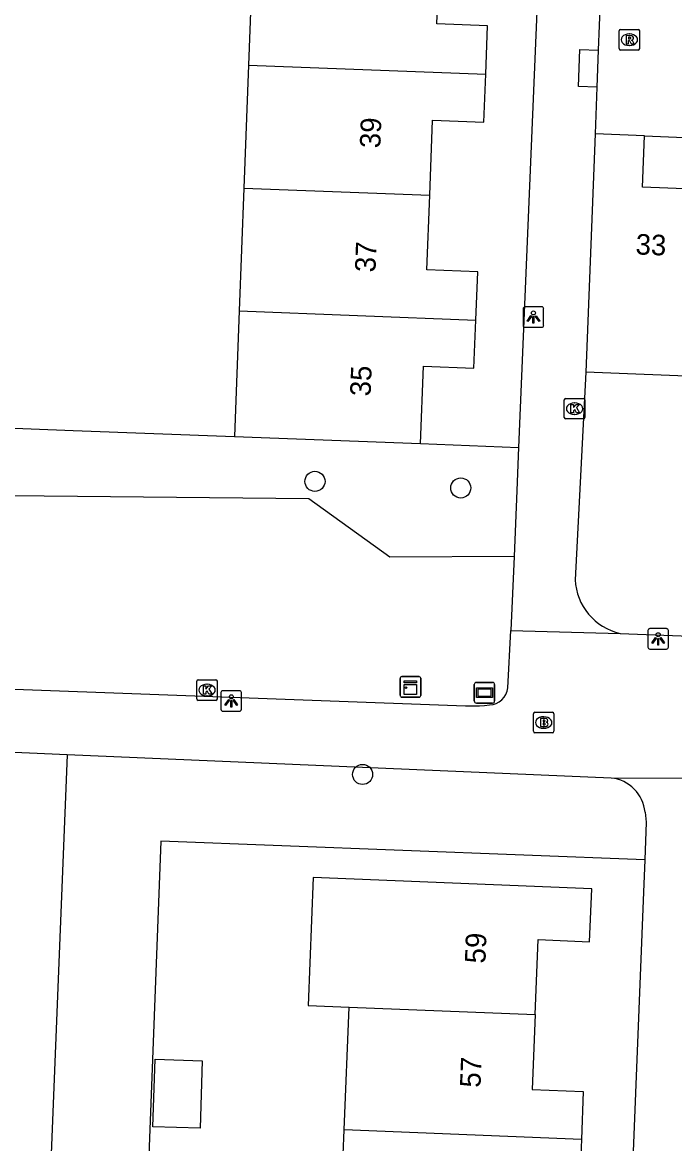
# Model space of a CAD drawing. Extents: x 160787 to 161428, y 386828 to 387483.
# Drawn here: x 161141.1 to 161172.8, y 387264.6 to 387319.2 of the extents above; entities that cross this region are included whole.
import ezdxf

# ---------------------------------------------------------------- set-up
doc = ezdxf.new("R2010")
doc.units = 0
for name, color, linetype in [('IMGEO_Boom', 7, 'Continuous'), ('IMGEO_Brandkraan', 7, 'Continuous'), ('IMGEO_Groenvoorziening', 7, 'Continuous'), ('IMGEO_Kast', 7, 'Continuous'), ('IMGEO_Kolk', 7, 'Continuous'), ('IMGEO_Lichtpunt', 7, 'Continuous'), ('IMGEO_Pand', 7, 'Continuous'), ('IMGEO_Pand_nummerreeks', 7, 'Continuous'), ('IMGEO_Rijbaan_lokaal_open', 7, 'Continuous'), ('IMGEO_Rioolput', 7, 'Continuous'), ('IMGEO_Straatnaambord', 7, 'Continuous'), ('IMGEO_Voetpad_open', 7, 'Continuous')]:
    doc.layers.add(name, color=color, linetype=linetype)

msp = doc.modelspace()

# ---------------------------------------------------------------- linework, layer by layer
at = {"layer": 'IMGEO_Boom'}
for centre in [(161155.308, 387296.861), (161162.4, 387296.541), (161157.626, 387282.603)]:
    msp.add_circle(centre, 0.489, dxfattribs=at)
at = {"layer": 'IMGEO_Brandkraan'}
for p, q in [((161165.935, 387284.701), (161165.935, 387285.553)), ((161166.01, 387285.627), (161166.862, 387285.627)), ((161166.423, 387285.407), (161166.448, 387285.407)), ((161166.936, 387285.553), (161166.936, 387284.701)), ((161166.862, 387284.627), (161166.01, 387284.627)), ((161166.446, 387284.847), (161166.421, 387284.847))]:
    msp.add_line(p, q, dxfattribs=at)
for points in [[(161165.935, 387284.701), (161165.935, 387285.553)], [(161166.01, 387285.627), (161166.862, 387285.627)], [(161166.936, 387285.553), (161166.936, 387284.701)], [(161166.283, 387285.327), (161166.283, 387284.927), (161166.496, 387284.927)], [(161166.514, 387285.327), (161166.283, 387285.327)], [(161166.462, 387285.246), (161166.408, 387285.246), (161166.408, 387285.17)], [(161166.408, 387285.17), (161166.461, 387285.17)], [(161166.47, 387285.094), (161166.408, 387285.094), (161166.408, 387285.013)], [(161166.408, 387285.013), (161166.47, 387285.013)], [(161166.862, 387284.627), (161166.01, 387284.627)]]:
    msp.add_lwpolyline(points, dxfattribs=at)
for centre, radius, start, end in [((161166.012, 387285.551), 0.0765, 91.552, 178.448), ((161166.012, 387285.551), 0.0765, 91.552, 178.448), ((161166.86, 387285.551), 0.0765, 1.552, 88.448), ((161166.86, 387285.551), 0.0765, 1.552, 88.448), ((161166.463, 387285.208), 0.0379, 267.8285, 90.9355), ((161166.471, 387285.053), 0.0404, 269.8759, 90.5077), ((161166.502, 387285.178), 0.251, 268.6676, 293.5347), ((161166.518, 387285.182), 0.145, 59.4692, 91.5367), ((161166.543, 387285.229), 0.0922, 285.5137, 58.1501), ((161166.548, 387285.037), 0.105, 301.3115, 78.989), ((161166.012, 387284.703), 0.0765, 181.552, 268.448), ((161166.012, 387284.703), 0.0765, 181.552, 268.448), ((161166.86, 387284.703), 0.0765, 271.552, 358.448), ((161166.86, 387284.703), 0.0765, 271.552, 358.448)]:
    msp.add_arc(centre, radius, start, end, dxfattribs=at)
for centre, major_axis, ratio, start_param, end_param in [((161166.422, 387285.127), (-0.387, 0.002), 0.722429, 4.712389, 7.853982), ((161166.447, 387285.127), (-0.39, 0.002), 0.717154, 1.570796, 4.712389)]:
    msp.add_ellipse(centre, major_axis=major_axis, ratio=ratio, start_param=start_param, end_param=end_param, dxfattribs=at)
at = {"layer": 'IMGEO_Groenvoorziening'}
for points in [[(161139.046, 387299.512), (161143.553, 387299.341), (161151.391, 387299.041)], [(161160.443, 387298.696), (161165.215, 387298.514)], [(161164.993, 387293.208), (161158.958, 387293.171), (161155.006, 387296.014), (161138.908, 387296.177)], [(161143.258, 387283.56), (161141.91, 387250), (161139.825, 387198.117), (161139.779, 387196.96), (161145.215, 387196.742), (161162.77, 387196.036), (161162.811, 387197.084)], [(161171.353, 387278.449), (161147.813, 387279.35), (161146.59, 387247.494), (161144.751, 387247.564), (161143.809, 387246.052), (161142.905, 387223.679), (161145.53, 387223.573), (161145.284, 387217.483), (161143.51, 387217.555), (161143.326, 387213), (161145.236, 387212.923), (161144.626, 387197.819), (161152.342, 387197.507), (161162.811, 387197.084)]]:
    msp.add_lwpolyline(points, dxfattribs=at)
at = {"layer": 'IMGEO_Kast'}
for p, q in [((161159.454, 387286.435), (161159.454, 387287.276)), ((161159.454, 387287.276), (161159.454, 387286.435)), ((161159.529, 387287.36), (161160.37, 387287.36)), ((161160.37, 387287.36), (161159.529, 387287.36)), ((161160.454, 387287.285), (161160.454, 387286.444)), ((161160.454, 387286.444), (161160.454, 387287.285)), ((161160.379, 387286.36), (161159.538, 387286.36)), ((161159.538, 387286.36), (161160.379, 387286.36))]:
    msp.add_line(p, q, dxfattribs=at)
for points in [[(161159.649, 387287.15), (161160.249, 387287.15), (161160.249, 387287.065), (161159.649, 387287.065), (161159.649, 387287.15)], [(161159.649, 387286.975), (161160.249, 387286.975), (161160.249, 387286.486), (161159.649, 387286.486), (161159.649, 387286.975)]]:
    msp.add_lwpolyline(points, dxfattribs=at)
msp.add_circle((161159.733, 387286.824), 0.0377, dxfattribs=at)
for centre, start, end in [((161159.532, 387287.282), 92.4484, 184.2845), ((161159.532, 387287.282), 92.4484, 184.2845), ((161160.376, 387287.282), 2.4484, 94.2845), ((161160.376, 387287.282), 2.4484, 94.2845), ((161159.532, 387286.438), 182.4484, 274.2845), ((161159.532, 387286.438), 182.4484, 274.2845), ((161160.376, 387286.438), 272.4484, 4.2845), ((161160.376, 387286.438), 272.4484, 4.2845)]:
    msp.add_arc(centre, 0.0779, start, end, dxfattribs=at)
at = {"layer": 'IMGEO_Kolk'}
for p, q in [((161167.439, 387299.973), (161167.439, 387300.825)), ((161167.514, 387300.899), (161168.366, 387300.899)), ((161168.44, 387300.825), (161168.44, 387299.973)), ((161167.927, 387300.679), (161167.952, 387300.679)), ((161168.366, 387299.899), (161167.514, 387299.899)), ((161167.95, 387300.119), (161167.925, 387300.119)), ((161149.558, 387286.281), (161149.558, 387287.133)), ((161149.633, 387287.207), (161150.485, 387287.207)), ((161150.559, 387287.133), (161150.559, 387286.281)), ((161150.046, 387286.987), (161150.071, 387286.987)), ((161150.485, 387286.207), (161149.633, 387286.207)), ((161150.069, 387286.427), (161150.044, 387286.427))]:
    msp.add_line(p, q, dxfattribs=at)
for points in [[(161167.439, 387299.973), (161167.439, 387300.825)], [(161167.514, 387300.899), (161168.366, 387300.899)], [(161168.44, 387300.825), (161168.44, 387299.973)], [(161167.76, 387300.599), (161167.883, 387300.599), (161167.883, 387300.448), (161168.013, 387300.599), (161168.177, 387300.599), (161168.031, 387300.448), (161168.184, 387300.199), (161168.032, 387300.199), (161167.947, 387300.363), (161167.883, 387300.296), (161167.883, 387300.199), (161167.76, 387300.199), (161167.76, 387300.599)], [(161168.366, 387299.899), (161167.514, 387299.899)], [(161149.558, 387286.281), (161149.558, 387287.133)], [(161149.633, 387287.207), (161150.485, 387287.207)], [(161150.559, 387287.133), (161150.559, 387286.281)], [(161149.879, 387286.907), (161150.002, 387286.907), (161150.002, 387286.756), (161150.132, 387286.907), (161150.296, 387286.907), (161150.15, 387286.756), (161150.303, 387286.507), (161150.151, 387286.507), (161150.066, 387286.671), (161150.002, 387286.604), (161150.002, 387286.507), (161149.879, 387286.507), (161149.879, 387286.907)], [(161150.485, 387286.207), (161149.633, 387286.207)]]:
    msp.add_lwpolyline(points, dxfattribs=at)
for centre, start, end in [((161167.516, 387300.823), 91.552, 178.448), ((161167.516, 387300.823), 91.552, 178.448), ((161168.364, 387300.823), 1.552, 88.448), ((161168.364, 387300.823), 1.552, 88.448), ((161167.516, 387299.975), 181.552, 268.448), ((161167.516, 387299.975), 181.552, 268.448), ((161168.364, 387299.975), 271.552, 358.448), ((161168.364, 387299.975), 271.552, 358.448), ((161149.635, 387287.131), 91.552, 178.448), ((161149.635, 387287.131), 91.552, 178.448), ((161150.483, 387287.131), 1.552, 88.448), ((161150.483, 387287.131), 1.552, 88.448), ((161149.635, 387286.283), 181.552, 268.448), ((161149.635, 387286.283), 181.552, 268.448), ((161150.483, 387286.283), 271.552, 358.448), ((161150.483, 387286.283), 271.552, 358.448)]:
    msp.add_arc(centre, 0.0765, start, end, dxfattribs=at)
for centre, major_axis, ratio, start_param, end_param in [((161167.926, 387300.399), (-0.387, 0.002), 0.722429, 4.712389, 7.853982), ((161167.951, 387300.399), (-0.39, 0.002), 0.717154, 1.570796, 4.712389), ((161150.045, 387286.707), (-0.387, 0.002), 0.722429, 4.712389, 7.853982), ((161150.07, 387286.707), (-0.39, 0.002), 0.717154, 1.570796, 4.712389)]:
    msp.add_ellipse(centre, major_axis=major_axis, ratio=ratio, start_param=start_param, end_param=end_param, dxfattribs=at)
at = {"layer": 'IMGEO_Lichtpunt'}
for p, q in [((161165.438, 387305.26), (161165.438, 387304.453)), ((161165.438, 387305.26), (161165.438, 387304.453)), ((161166.34, 387305.355), (161165.532, 387305.355)), ((161166.34, 387305.355), (161165.532, 387305.355)), ((161166.434, 387304.453), (161166.434, 387305.26)), ((161166.434, 387304.453), (161166.434, 387305.26)), ((161165.532, 387304.359), (161166.34, 387304.359)), ((161165.532, 387304.359), (161166.34, 387304.359)), ((161171.504, 387289.6), (161171.504, 387288.793)), ((161171.504, 387289.6), (161171.504, 387288.793)), ((161172.406, 387289.695), (161171.598, 387289.695)), ((161172.406, 387289.695), (161171.598, 387289.695)), ((161172.5, 387288.793), (161172.5, 387289.6)), ((161172.5, 387288.793), (161172.5, 387289.6)), ((161171.598, 387288.699), (161172.406, 387288.699)), ((161171.598, 387288.699), (161172.406, 387288.699)), ((161150.737, 387286.581), (161150.737, 387285.774)), ((161150.737, 387286.581), (161150.737, 387285.774)), ((161151.639, 387286.676), (161150.831, 387286.676)), ((161151.639, 387286.676), (161150.831, 387286.676)), ((161151.733, 387285.774), (161151.733, 387286.581)), ((161151.733, 387285.774), (161151.733, 387286.581)), ((161150.831, 387285.68), (161151.639, 387285.68)), ((161150.831, 387285.68), (161151.639, 387285.68))]:
    msp.add_line(p, q, dxfattribs=at)
for points in [[(161165.812, 387304.924), (161165.851, 387304.896), (161165.663, 387304.634), (161165.625, 387304.661), (161165.812, 387304.924)], [(161165.914, 387304.876), (161165.961, 387304.876), (161165.961, 387304.554), (161165.914, 387304.554), (161165.914, 387304.876)], [(161166.024, 387304.896), (161166.062, 387304.923), (161166.249, 387304.661), (161166.21, 387304.633), (161166.024, 387304.896)], [(161171.878, 387289.264), (161171.917, 387289.236), (161171.729, 387288.974), (161171.691, 387289.001), (161171.878, 387289.264)], [(161172.09, 387289.236), (161172.128, 387289.263), (161172.315, 387289.001), (161172.276, 387288.973), (161172.09, 387289.236)], [(161171.98, 387289.216), (161172.027, 387289.216), (161172.027, 387288.894), (161171.98, 387288.894), (161171.98, 387289.216)], [(161151.111, 387286.245), (161151.15, 387286.217), (161150.962, 387285.955), (161150.924, 387285.982), (161151.111, 387286.245)], [(161151.213, 387286.197), (161151.26, 387286.197), (161151.26, 387285.875), (161151.213, 387285.875), (161151.213, 387286.197)], [(161151.323, 387286.217), (161151.361, 387286.244), (161151.548, 387285.982), (161151.509, 387285.954), (161151.323, 387286.217)]]:
    msp.add_lwpolyline(points, dxfattribs=at)
for centre in [(161165.937, 387305.058), (161172.003, 387289.398), (161151.236, 387286.379)]:
    msp.add_circle(centre, 0.0994, dxfattribs=at)
for centre, start, end in [((161165.532, 387305.26), 90, 180), ((161165.532, 387305.26), 90, 180), ((161166.34, 387305.26), 0, 90), ((161166.34, 387305.26), 0, 90), ((161165.532, 387304.453), 180, 270), ((161165.532, 387304.453), 180, 270), ((161166.34, 387304.453), 270, 0), ((161166.34, 387304.453), 270, 360), ((161171.598, 387289.6), 90, 180), ((161171.598, 387289.6), 90, 180), ((161172.406, 387289.6), 0, 90), ((161172.406, 387289.6), 0, 90), ((161171.598, 387288.793), 180, 270), ((161171.598, 387288.793), 180, 270), ((161172.406, 387288.793), 270, 0), ((161172.406, 387288.793), 270, 360), ((161150.831, 387286.581), 90, 180), ((161150.831, 387286.581), 90, 180), ((161151.639, 387286.581), 0, 90), ((161151.639, 387286.581), 0, 90), ((161150.831, 387285.774), 180, 270), ((161150.831, 387285.774), 180, 270), ((161151.639, 387285.774), 270, 0), ((161151.639, 387285.774), 270, 360)]:
    msp.add_arc(centre, 0.0946, start, end, dxfattribs=at)
at = {"layer": 'IMGEO_Pand'}
for points in [[(161152.31, 387323.131), (161152.081, 387317.118)], [(161163.618, 387316.678), (161163.708, 387319.022), (161161.238, 387319.116), (161161.378, 387322.785)], [(161152.081, 387317.118), (161151.852, 387311.135)], [(161152.081, 387317.118), (161163.618, 387316.678)], [(161160.89, 387310.79), (161161.029, 387314.43), (161163.529, 387314.335), (161163.618, 387316.678)], [(161168.933, 387313.767), (161168.48, 387302.177)], [(161171.343, 387313.673), (161168.933, 387313.767)], [(161174.935, 387311.032), (161171.246, 387311.176), (161171.343, 387313.673)], [(161151.852, 387311.135), (161151.624, 387305.151)], [(161151.852, 387311.135), (161160.89, 387310.79)], [(161163.135, 387304.712), (161163.224, 387307.055), (161160.751, 387307.149), (161160.89, 387310.79)], [(161151.624, 387305.151), (161151.391, 387299.041)], [(161151.624, 387305.151), (161163.135, 387304.712)], [(161160.443, 387298.696), (161160.586, 387302.463), (161163.045, 387302.369), (161163.135, 387304.712)], [(161174.579, 387301.938), (161168.48, 387302.177)], [(161151.391, 387299.041), (161160.443, 387298.696)], [(161166.02, 387270.922), (161166.166, 387274.565), (161168.668, 387274.465), (161168.771, 387277.039), (161157.214, 387277.502), (161155.223, 387277.582), (161154.974, 387271.365), (161156.965, 387271.285)], [(161156.726, 387265.307), (161156.965, 387271.285)], [(161156.965, 387271.285), (161166.02, 387270.922)], [(161166.02, 387270.922), (161165.874, 387267.279), (161168.363, 387267.179), (161168.27, 387264.845)], [(161147.429, 387265.462), (161147.528, 387268.745), (161149.818, 387268.675), (161149.719, 387265.392), (161147.429, 387265.462)], [(161156.486, 387259.313), (161156.726, 387265.307)], [(161168.27, 387264.845), (161156.726, 387265.307)], [(161168.27, 387264.845), (161168.177, 387262.51), (161165.644, 387262.611), (161165.498, 387258.952)]]:
    msp.add_lwpolyline(points, dxfattribs=at)
at = {"layer": 'IMGEO_Rijbaan_lokaal_open'}
for points in [[(161169.235, 387321.452), (161169.093, 387317.844)], [(161169.093, 387317.844), (161169.022, 387316.036)], [(161169.022, 387316.036), (161168.933, 387313.767)], [(161171.343, 387313.673), (161178.722, 387313.364)]]:
    msp.add_lwpolyline(points, dxfattribs=at)
at = {"layer": 'IMGEO_Rioolput'}
for p, q in [((161170.103, 387317.923), (161170.103, 387318.775)), ((161170.178, 387318.849), (161171.03, 387318.849)), ((161171.104, 387318.775), (161171.104, 387317.923)), ((161170.591, 387318.629), (161170.616, 387318.629)), ((161171.03, 387317.849), (161170.178, 387317.849)), ((161170.614, 387318.069), (161170.589, 387318.069))]:
    msp.add_line(p, q, dxfattribs=at)
for points in [[(161170.103, 387317.923), (161170.103, 387318.775)], [(161170.178, 387318.849), (161171.03, 387318.849)], [(161171.104, 387318.775), (161171.104, 387317.923)], [(161170.692, 387318.547), (161170.44, 387318.549), (161170.44, 387318.149)], [(161170.44, 387318.149), (161170.564, 387318.149), (161170.564, 387318.311), (161170.575, 387318.311)], [(161170.618, 387318.468), (161170.564, 387318.468), (161170.564, 387318.387)], [(161170.564, 387318.387), (161170.616, 387318.387)], [(161170.622, 387318.282), (161170.693, 387318.149), (161170.833, 387318.149), (161170.768, 387318.275)], [(161171.03, 387317.849), (161170.178, 387317.849)]]:
    msp.add_lwpolyline(points, dxfattribs=at)
for centre, radius, start, end in [((161170.18, 387318.773), 0.0765, 91.552, 178.448), ((161170.18, 387318.773), 0.0765, 91.552, 178.448), ((161171.028, 387318.773), 0.0765, 1.552, 88.448), ((161171.028, 387318.773), 0.0765, 1.552, 88.448), ((161170.574, 387318.258), 0.0533, 26.0293, 88.6989), ((161170.6, 387318.576), 0.19, 274.7715, 282.9687), ((161170.624, 387318.372), 0.0964, 77.0061, 93.1865), ((161170.638, 387318.429), 0.0378, 276.6634, 79.6772), ((161170.691, 387318.437), 0.109, 350.3612, 89.416), ((161170.689, 387318.437), 0.112, 277.5842, 350.9817), ((161170.673, 387318.222), 0.108, 29.5134, 73.7905), ((161170.18, 387317.925), 0.0765, 181.552, 268.448), ((161170.18, 387317.925), 0.0765, 181.552, 268.448), ((161171.028, 387317.925), 0.0765, 271.552, 358.448), ((161171.028, 387317.925), 0.0765, 271.552, 358.448)]:
    msp.add_arc(centre, radius, start, end, dxfattribs=at)
for centre, major_axis, ratio, start_param, end_param in [((161170.59, 387318.349), (-0.387, 0.002), 0.722429, 4.712389, 7.853982), ((161170.615, 387318.349), (-0.39, 0.002), 0.717154, 1.570796, 4.712389)]:
    msp.add_ellipse(centre, major_axis=major_axis, ratio=ratio, start_param=start_param, end_param=end_param, dxfattribs=at)
at = {"layer": 'IMGEO_Straatnaambord'}
for p, q in [((161163.159, 387287.076), (161163.949, 387287.076)), ((161163.949, 387287.076), (161163.159, 387287.076)), ((161163.059, 387286.176), (161163.059, 387286.976)), ((161163.059, 387286.976), (161163.059, 387286.176)), ((161164.049, 387286.976), (161164.049, 387286.176)), ((161164.049, 387286.176), (161164.049, 387286.976)), ((161163.949, 387286.076), (161163.159, 387286.076)), ((161163.159, 387286.076), (161163.949, 387286.076))]:
    msp.add_line(p, q, dxfattribs=at)
for points in [[(161163.16, 387286.808), (161163.948, 387286.808), (161163.948, 387286.344), (161163.16, 387286.344), (161163.16, 387286.808)], [(161163.225, 387286.743), (161163.225, 387286.409), (161163.883, 387286.409), (161163.883, 387286.743), (161163.225, 387286.743)]]:
    msp.add_lwpolyline(points, dxfattribs=at)
for centre, start, end in [((161163.159, 387286.976), 90, 180), ((161163.159, 387286.976), 90, 180), ((161163.949, 387286.976), 0, 90), ((161163.949, 387286.976), 360, 90), ((161163.159, 387286.176), 180, 270), ((161163.159, 387286.176), 180, 270), ((161163.949, 387286.176), 270, 0), ((161163.949, 387286.176), 270, 0)]:
    msp.add_arc(centre, 0.1, start, end, dxfattribs=at)
at = {"layer": 'IMGEO_Voetpad_open'}
for points in [[(161166.813, 387336.716), (161165.215, 387298.514)], [(161169.022, 387316.036), (161168.124, 387316.072), (161168.195, 387317.88), (161169.093, 387317.844)], [(161168.48, 387302.177), (161167.965, 387292.078)], [(161165.215, 387298.514), (161165.127, 387296.415), (161164.993, 387293.208)], [(161164.993, 387293.208), (161164.829, 387289.6)], [(161164.69, 387286.821), (161164.829, 387289.6)], [(161164.829, 387289.6), (161170.163, 387289.466)], [(161170.163, 387289.466), (161204.081, 387288.161), (161247.486, 387286.367), (161267.914, 387285.628)], [(161140.247, 387286.767), (161162.637, 387285.947), (161163.314, 387285.947), (161163.563, 387285.964), (161163.803, 387285.99)], [(161143.258, 387283.56), (161137.745, 387283.796)], [(161169.71, 387282.428), (161143.258, 387283.56)], [(161181.145, 387282.379), (161169.71, 387282.428)], [(161171.366, 387280.761), (161171.423, 387280.284), (161171.353, 387278.449)], [(161171.353, 387278.449), (161171.292, 387276.874), (161170.226, 387250), (161169.709, 387236.985), (161169.695, 387236.621)]]:
    msp.add_lwpolyline(points, dxfattribs=at)
for centre, radius, start, end in [((161170.764, 387292.203), 2.802, 182.5554, 257.6059), ((161163.775, 387286.909), 0.92, 271.7735, 354.4926), ((161169.529, 387280.592), 1.845, 5.2477, 84.373)]:
    msp.add_arc(centre, radius, start, end, dxfattribs=at)

# ---------------------------------------------------------------- texts
at = {"layer": 'IMGEO_Pand_nummerreeks'}
for s, rotation, p in [('39', 87.7523, (161158.485, 387313.059)), ('33', 357.7066, (161170.894, 387307.906)), ('37', 87.7523, (161158.249, 387307.023)), ('35', 87.7523, (161158.012, 387300.987)), ('59', 87.7198, (161163.597, 387273.392)), ('57', 87.7194, (161163.358, 387267.35))]:
    msp.add_text(s, height=1, rotation=rotation, dxfattribs=at).set_placement(p)

doc.saveas('drawing.dxf')
